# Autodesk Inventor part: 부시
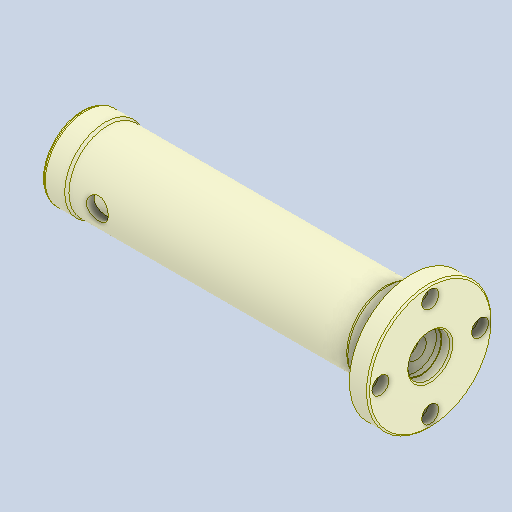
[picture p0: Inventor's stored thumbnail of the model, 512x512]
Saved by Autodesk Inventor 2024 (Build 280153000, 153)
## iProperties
Created: 2024-07
Part Number: 부시
Material: 강철, 탄소
Document SubType Name: Modeling
Designer: com
Density: 7.85 g/cm^3
Appearance: 기본값
Author: jhkim
Sending System: Autodesk Inventor 2025
Preprocessor: ST-DEVELOPER v20
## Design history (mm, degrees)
feature "솔리드1"
node "솔리드2"
